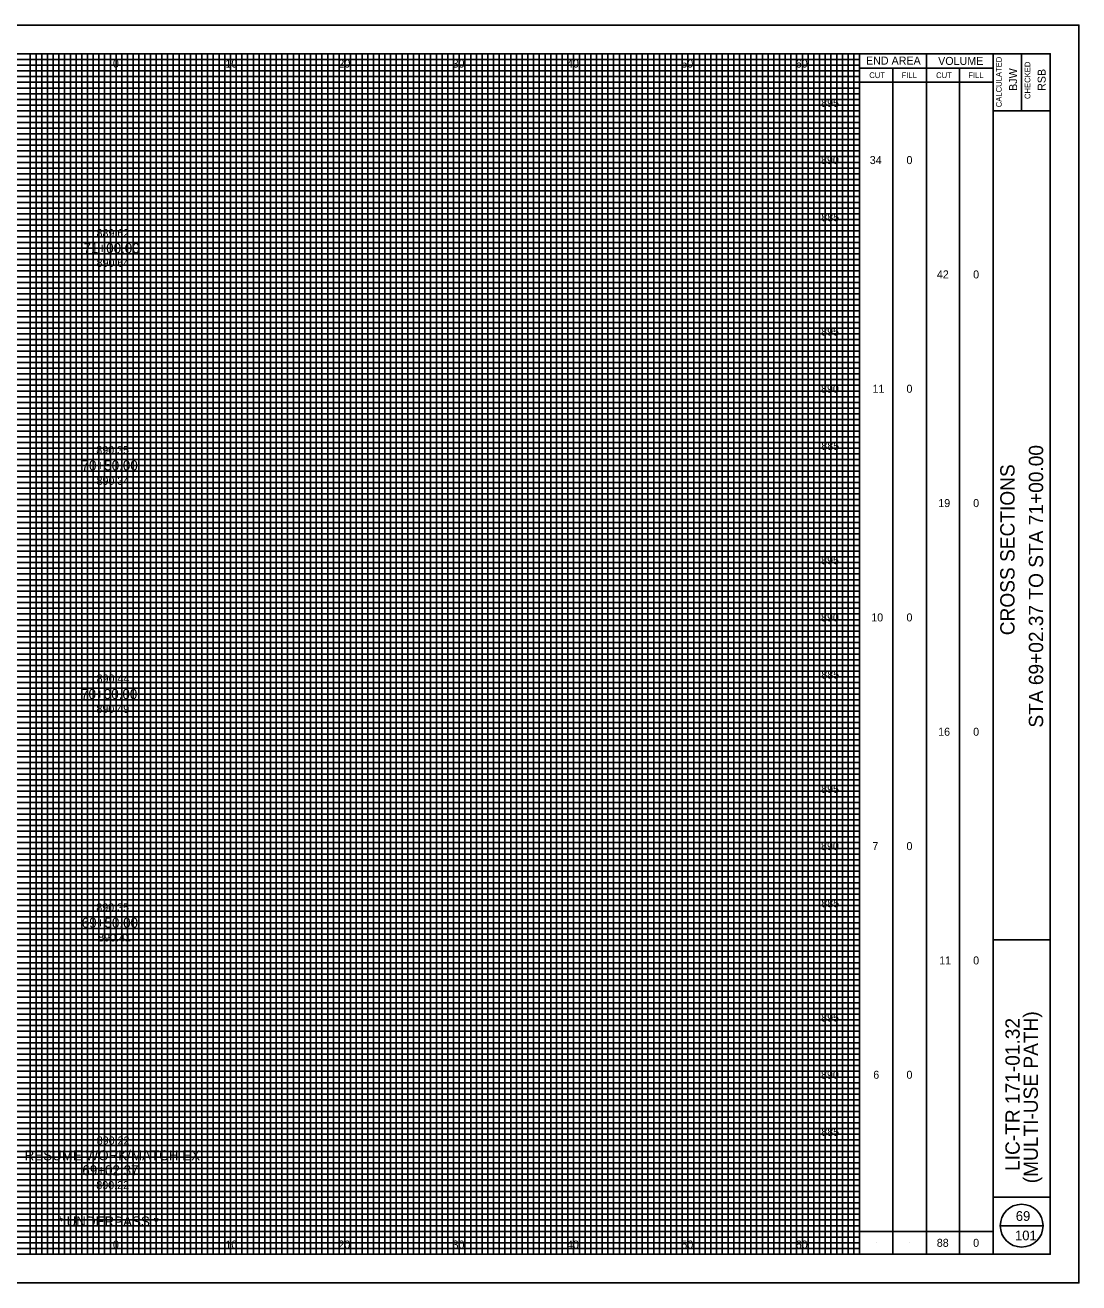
# Model space of a CAD drawing. Extents: x -10 to 160, y -2 to 3672.
# Drawn here: x 67.9 to 160, y -2.5 to 107.5 of the extents above; entities that cross this region are included whole.
import ezdxf

# ---------------------------------------------------------------- set-up
doc = ezdxf.new("R2010")
doc.units = 0
for name, color, linetype in [('SH_Border', 7, 'Continuous'), ('SH_Cut_Line', 7, 'Continuous'), ('SH_Data', 7, 'Continuous'), ('SH_Major_Grid_Line', 7, 'Continuous'), ('SH_Minor_Grid_Line', 7, 'Continuous'), ('SH_Text', 7, 'Continuous'), ('TX_P_10', 7, 'Continuous'), ('TX_X_10', 7, 'Continuous')]:
    doc.layers.add(name, color=color, linetype=linetype)

msp = doc.modelspace()

# ---------------------------------------------------------------- linework, layer by layer
at = {"layer": 'SH_Border'}
for p, q in [((152.5, 0), (152.5, 105)), ((155, 105), (155, 100)), ((152.5, 100), (157.5, 100)), ((152.5, 27.5), (157.5, 27.5)), ((152.5, 5), (157.5, 5))]:
    msp.add_line(p, q, dxfattribs=at)
msp.add_lwpolyline([(0, 105), (157.5, 105), (157.5, 0), (0, 0)], close=True, dxfattribs=at)
at = {"layer": 'SH_Cut_Line'}
msp.add_lwpolyline([(-10, -2.5), (160, -2.5), (160, 107.5), (-10, 107.5)], close=True, dxfattribs=at)
at = {"layer": 'SH_Data'}
for p, q in [((140.83, 0), (140.83, 105)), ((146.67, 0), (146.67, 105)), ((140.83, 103.75), (152.5, 103.75)), ((143.75, 0), (143.75, 103.75)), ((149.58, 0), (149.58, 103.75)), ((140.83, 102.5), (152.5, 102.5)), ((153.12, 2.5), (156.88, 2.5)), ((140.83, 2), (152.5, 2)), ((142.29, 1), (142.29, 1)), ((145.21, 1), (145.21, 1)), ((148.12, 1), (148.12, 1)), ((151.04, 1), (151.04, 1))]:
    msp.add_line(p, q, dxfattribs=at)
msp.add_circle((155, 2.5), 1.87, dxfattribs=at)
at = {"layer": 'SH_Major_Grid_Line'}
for p, q in [((70.83, 0), (70.83, 105)), ((75.83, 0), (75.83, 105)), ((80.83, 0), (80.83, 105)), ((85.83, 0), (85.83, 105)), ((90.83, 0), (90.83, 105)), ((95.83, 0), (95.83, 105)), ((100.83, 0), (100.83, 105)), ((105.83, 0), (105.83, 105)), ((110.83, 0), (110.83, 105)), ((115.83, 0), (115.83, 105)), ((120.83, 0), (120.83, 105)), ((125.83, 0), (125.83, 105)), ((130.83, 0), (130.83, 105)), ((135.83, 0), (135.83, 105)), ((5.83, 100), (140.83, 100)), ((5.83, 95), (140.83, 95)), ((5.83, 90), (140.83, 90)), ((5.83, 85), (140.83, 85)), ((5.83, 80), (140.83, 80)), ((5.83, 75), (140.83, 75)), ((5.83, 70), (140.83, 70)), ((5.83, 65), (140.83, 65)), ((5.83, 60), (140.83, 60)), ((5.83, 55), (140.83, 55)), ((5.83, 50), (140.83, 50)), ((5.83, 45), (140.83, 45)), ((5.83, 40), (140.83, 40)), ((5.83, 35), (140.83, 35)), ((5.83, 30), (140.83, 30)), ((5.83, 25), (140.83, 25)), ((5.83, 20), (140.83, 20)), ((5.83, 15), (140.83, 15)), ((5.83, 10), (140.83, 10)), ((5.83, 5), (140.83, 5))]:
    msp.add_line(p, q, dxfattribs=at)
at = {"layer": 'SH_Minor_Grid_Line'}
for p, q in [((68.33, 0), (68.33, 105)), ((68.83, 0), (68.83, 105)), ((69.33, 0), (69.33, 105)), ((69.83, 0), (69.83, 105)), ((70.33, 0), (70.33, 105)), ((71.33, 0), (71.33, 105)), ((71.83, 0), (71.83, 105)), ((72.33, 0), (72.33, 105)), ((72.83, 0), (72.83, 105)), ((73.33, 0), (73.33, 105)), ((73.83, 0), (73.83, 105)), ((74.33, 0), (74.33, 105)), ((74.83, 0), (74.83, 105)), ((75.33, 0), (75.33, 105)), ((76.33, 0), (76.33, 105)), ((76.83, 0), (76.83, 105)), ((77.33, 0), (77.33, 105)), ((77.83, 0), (77.83, 105)), ((78.33, 0), (78.33, 105)), ((78.83, 0), (78.83, 105)), ((79.33, 0), (79.33, 105)), ((79.83, 0), (79.83, 105)), ((80.33, 0), (80.33, 105)), ((81.33, 0), (81.33, 105)), ((81.83, 0), (81.83, 105)), ((82.33, 0), (82.33, 105)), ((82.83, 0), (82.83, 105)), ((83.33, 0), (83.33, 105)), ((83.83, 0), (83.83, 105)), ((84.33, 0), (84.33, 105)), ((84.83, 0), (84.83, 105)), ((85.33, 0), (85.33, 105)), ((86.33, 0), (86.33, 105)), ((86.83, 0), (86.83, 105)), ((87.33, 0), (87.33, 105)), ((87.83, 0), (87.83, 105)), ((88.33, 0), (88.33, 105)), ((88.83, 0), (88.83, 105)), ((89.33, 0), (89.33, 105)), ((89.83, 0), (89.83, 105)), ((90.33, 0), (90.33, 105)), ((91.33, 0), (91.33, 105)), ((91.83, 0), (91.83, 105)), ((92.33, 0), (92.33, 105)), ((92.83, 0), (92.83, 105)), ((93.33, 0), (93.33, 105)), ((93.83, 0), (93.83, 105)), ((94.33, 0), (94.33, 105)), ((94.83, 0), (94.83, 105)), ((95.33, 0), (95.33, 105)), ((96.33, 0), (96.33, 105)), ((96.83, 0), (96.83, 105)), ((97.33, 0), (97.33, 105)), ((97.83, 0), (97.83, 105)), ((98.33, 0), (98.33, 105)), ((98.83, 0), (98.83, 105)), ((99.33, 0), (99.33, 105)), ((99.83, 0), (99.83, 105)), ((100.33, 0), (100.33, 105)), ((101.33, 0), (101.33, 105)), ((101.83, 0), (101.83, 105)), ((102.33, 0), (102.33, 105)), ((102.83, 0), (102.83, 105)), ((103.33, 0), (103.33, 105)), ((103.83, 0), (103.83, 105)), ((104.33, 0), (104.33, 105)), ((104.83, 0), (104.83, 105)), ((105.33, 0), (105.33, 105)), ((106.33, 0), (106.33, 105)), ((106.83, 0), (106.83, 105)), ((107.33, 0), (107.33, 105)), ((107.83, 0), (107.83, 105)), ((108.33, 0), (108.33, 105)), ((108.83, 0), (108.83, 105)), ((109.33, 0), (109.33, 105)), ((109.83, 0), (109.83, 105)), ((110.33, 0), (110.33, 105)), ((111.33, 0), (111.33, 105)), ((111.83, 0), (111.83, 105)), ((112.33, 0), (112.33, 105)), ((112.83, 0), (112.83, 105)), ((113.33, 0), (113.33, 105)), ((113.83, 0), (113.83, 105)), ((114.33, 0), (114.33, 105)), ((114.83, 0), (114.83, 105)), ((115.33, 0), (115.33, 105)), ((116.33, 0), (116.33, 105)), ((116.83, 0), (116.83, 105)), ((117.33, 0), (117.33, 105)), ((117.83, 0), (117.83, 105)), ((118.33, 0), (118.33, 105)), ((118.83, 0), (118.83, 105)), ((119.33, 0), (119.33, 105)), ((119.83, 0), (119.83, 105)), ((120.33, 0), (120.33, 105)), ((121.33, 0), (121.33, 105)), ((121.83, 0), (121.83, 105)), ((122.33, 0), (122.33, 105)), ((122.83, 0), (122.83, 105)), ((123.33, 0), (123.33, 105)), ((123.83, 0), (123.83, 105)), ((124.33, 0), (124.33, 105)), ((124.83, 0), (124.83, 105)), ((125.33, 0), (125.33, 105)), ((126.33, 0), (126.33, 105)), ((126.83, 0), (126.83, 105)), ((127.33, 0), (127.33, 105)), ((127.83, 0), (127.83, 105)), ((128.33, 0), (128.33, 105)), ((128.83, 0), (128.83, 105)), ((129.33, 0), (129.33, 105)), ((129.83, 0), (129.83, 105)), ((130.33, 0), (130.33, 105)), ((131.33, 0), (131.33, 105)), ((131.83, 0), (131.83, 105)), ((132.33, 0), (132.33, 105)), ((132.83, 0), (132.83, 105)), ((133.33, 0), (133.33, 105)), ((133.83, 0), (133.83, 105)), ((134.33, 0), (134.33, 105)), ((134.83, 0), (134.83, 105)), ((135.33, 0), (135.33, 105)), ((136.33, 0), (136.33, 105)), ((136.83, 0), (136.83, 105)), ((137.33, 0), (137.33, 105)), ((137.83, 0), (137.83, 105)), ((138.33, 0), (138.33, 105)), ((138.83, 0), (138.83, 105)), ((139.33, 0), (139.33, 105)), ((139.83, 0), (139.83, 105)), ((140.33, 0), (140.33, 105)), ((5.83, 104.5), (140.83, 104.5)), ((5.83, 104), (140.83, 104)), ((5.83, 103.5), (140.83, 103.5)), ((5.83, 103), (140.83, 103)), ((5.83, 102.5), (140.83, 102.5)), ((5.83, 102), (140.83, 102)), ((5.83, 101.5), (140.83, 101.5)), ((5.83, 101), (140.83, 101)), ((5.83, 100.5), (140.83, 100.5)), ((5.83, 99.5), (140.83, 99.5)), ((5.83, 99), (140.83, 99)), ((5.83, 98.5), (140.83, 98.5)), ((5.83, 98), (140.83, 98)), ((5.83, 97.5), (140.83, 97.5)), ((5.83, 97), (140.83, 97)), ((5.83, 96.5), (140.83, 96.5)), ((5.83, 96), (140.83, 96)), ((5.83, 95.5), (140.83, 95.5)), ((5.83, 94.5), (140.83, 94.5)), ((5.83, 94), (140.83, 94)), ((5.83, 93.5), (140.83, 93.5)), ((5.83, 93), (140.83, 93)), ((5.83, 92.5), (140.83, 92.5)), ((5.83, 92), (140.83, 92)), ((5.83, 91.5), (140.83, 91.5)), ((5.83, 91), (140.83, 91)), ((5.83, 90.5), (140.83, 90.5)), ((5.83, 89.5), (140.83, 89.5)), ((5.83, 89), (140.83, 89)), ((5.83, 88.5), (140.83, 88.5)), ((5.83, 88), (140.83, 88)), ((5.83, 87.5), (140.83, 87.5)), ((5.83, 87), (140.83, 87)), ((5.83, 86.5), (140.83, 86.5)), ((5.83, 86), (140.83, 86)), ((5.83, 85.5), (140.83, 85.5)), ((5.83, 84.5), (140.83, 84.5)), ((5.83, 84), (140.83, 84)), ((5.83, 83.5), (140.83, 83.5)), ((5.83, 83), (140.83, 83)), ((5.83, 82.5), (140.83, 82.5)), ((5.83, 82), (140.83, 82)), ((5.83, 81.5), (140.83, 81.5)), ((5.83, 81), (140.83, 81)), ((5.83, 80.5), (140.83, 80.5)), ((5.83, 79.5), (140.83, 79.5)), ((5.83, 79), (140.83, 79)), ((5.83, 78.5), (140.83, 78.5)), ((5.83, 78), (140.83, 78)), ((5.83, 77.5), (140.83, 77.5)), ((5.83, 77), (140.83, 77)), ((5.83, 76.5), (140.83, 76.5)), ((5.83, 76), (140.83, 76)), ((5.83, 75.5), (140.83, 75.5)), ((5.83, 74.5), (140.83, 74.5)), ((5.83, 74), (140.83, 74)), ((5.83, 73.5), (140.83, 73.5)), ((5.83, 73), (140.83, 73)), ((5.83, 72.5), (140.83, 72.5)), ((5.83, 72), (140.83, 72)), ((5.83, 71.5), (140.83, 71.5)), ((5.83, 71), (140.83, 71)), ((5.83, 70.5), (140.83, 70.5)), ((5.83, 69.5), (140.83, 69.5)), ((5.83, 69), (140.83, 69)), ((5.83, 68.5), (140.83, 68.5)), ((5.83, 68), (140.83, 68)), ((5.83, 67.5), (140.83, 67.5)), ((5.83, 67), (140.83, 67)), ((5.83, 66.5), (140.83, 66.5)), ((5.83, 66), (140.83, 66)), ((5.83, 65.5), (140.83, 65.5)), ((5.83, 64.5), (140.83, 64.5)), ((5.83, 64), (140.83, 64)), ((5.83, 63.5), (140.83, 63.5)), ((5.83, 63), (140.83, 63)), ((5.83, 62.5), (140.83, 62.5)), ((5.83, 62), (140.83, 62)), ((5.83, 61.5), (140.83, 61.5)), ((5.83, 61), (140.83, 61)), ((5.83, 60.5), (140.83, 60.5)), ((5.83, 59.5), (140.83, 59.5)), ((5.83, 59), (140.83, 59)), ((5.83, 58.5), (140.83, 58.5)), ((5.83, 58), (140.83, 58)), ((5.83, 57.5), (140.83, 57.5)), ((5.83, 57), (140.83, 57)), ((5.83, 56.5), (140.83, 56.5)), ((5.83, 56), (140.83, 56)), ((5.83, 55.5), (140.83, 55.5)), ((5.83, 54.5), (140.83, 54.5)), ((5.83, 54), (140.83, 54)), ((5.83, 53.5), (140.83, 53.5)), ((5.83, 53), (140.83, 53)), ((5.83, 52.5), (140.83, 52.5)), ((5.83, 52), (140.83, 52)), ((5.83, 51.5), (140.83, 51.5)), ((5.83, 51), (140.83, 51)), ((5.83, 50.5), (140.83, 50.5)), ((5.83, 49.5), (140.83, 49.5)), ((5.83, 49), (140.83, 49)), ((5.83, 48.5), (140.83, 48.5)), ((5.83, 48), (140.83, 48)), ((5.83, 47.5), (140.83, 47.5)), ((5.83, 47), (140.83, 47)), ((5.83, 46.5), (140.83, 46.5)), ((5.83, 46), (140.83, 46)), ((5.83, 45.5), (140.83, 45.5)), ((5.83, 44.5), (140.83, 44.5)), ((5.83, 44), (140.83, 44)), ((5.83, 43.5), (140.83, 43.5)), ((5.83, 43), (140.83, 43)), ((5.83, 42.5), (140.83, 42.5)), ((5.83, 42), (140.83, 42)), ((5.83, 41.5), (140.83, 41.5)), ((5.83, 41), (140.83, 41)), ((5.83, 40.5), (140.83, 40.5)), ((5.83, 39.5), (140.83, 39.5)), ((5.83, 39), (140.83, 39)), ((5.83, 38.5), (140.83, 38.5)), ((5.83, 38), (140.83, 38)), ((5.83, 37.5), (140.83, 37.5)), ((5.83, 37), (140.83, 37)), ((5.83, 36.5), (140.83, 36.5)), ((5.83, 36), (140.83, 36)), ((5.83, 35.5), (140.83, 35.5)), ((5.83, 34.5), (140.83, 34.5)), ((5.83, 34), (140.83, 34)), ((5.83, 33.5), (140.83, 33.5)), ((5.83, 33), (140.83, 33)), ((5.83, 32.5), (140.83, 32.5)), ((5.83, 32), (140.83, 32)), ((5.83, 31.5), (140.83, 31.5)), ((5.83, 31), (140.83, 31)), ((5.83, 30.5), (140.83, 30.5)), ((5.83, 29.5), (140.83, 29.5)), ((5.83, 29), (140.83, 29)), ((5.83, 28.5), (140.83, 28.5)), ((5.83, 28), (140.83, 28)), ((5.83, 27.5), (140.83, 27.5)), ((5.83, 27), (140.83, 27)), ((5.83, 26.5), (140.83, 26.5)), ((5.83, 26), (140.83, 26)), ((5.83, 25.5), (140.83, 25.5)), ((5.83, 24.5), (140.83, 24.5)), ((5.83, 24), (140.83, 24)), ((5.83, 23.5), (140.83, 23.5)), ((5.83, 23), (140.83, 23)), ((5.83, 22.5), (140.83, 22.5)), ((5.83, 22), (140.83, 22)), ((5.83, 21.5), (140.83, 21.5)), ((5.83, 21), (140.83, 21)), ((5.83, 20.5), (140.83, 20.5)), ((5.83, 19.5), (140.83, 19.5)), ((5.83, 19), (140.83, 19)), ((5.83, 18.5), (140.83, 18.5)), ((5.83, 18), (140.83, 18)), ((5.83, 17.5), (140.83, 17.5)), ((5.83, 17), (140.83, 17)), ((5.83, 16.5), (140.83, 16.5)), ((5.83, 16), (140.83, 16)), ((5.83, 15.5), (140.83, 15.5)), ((5.83, 14.5), (140.83, 14.5)), ((5.83, 14), (140.83, 14)), ((5.83, 13.5), (140.83, 13.5)), ((5.83, 13), (140.83, 13)), ((5.83, 12.5), (140.83, 12.5)), ((5.83, 12), (140.83, 12)), ((5.83, 11.5), (140.83, 11.5)), ((5.83, 11), (140.83, 11)), ((5.83, 10.5), (140.83, 10.5)), ((5.83, 9.5), (140.83, 9.5)), ((5.83, 9), (140.83, 9)), ((5.83, 8.5), (140.83, 8.5)), ((5.83, 8), (140.83, 8)), ((5.83, 7.5), (140.83, 7.5)), ((5.83, 7), (140.83, 7)), ((5.83, 6.5), (140.83, 6.5)), ((5.83, 6), (140.83, 6)), ((5.83, 5.5), (140.83, 5.5)), ((5.83, 4.5), (140.83, 4.5)), ((5.83, 4), (140.83, 4)), ((5.83, 3.5), (140.83, 3.5)), ((5.83, 3), (140.83, 3)), ((5.83, 2.5), (140.83, 2.5)), ((5.83, 2), (140.83, 2)), ((5.83, 1.5), (140.83, 1.5)), ((5.83, 1), (140.83, 1)), ((5.83, 0.5), (140.83, 0.5))]:
    msp.add_line(p, q, dxfattribs=at)

# ---------------------------------------------------------------- texts
at = {"layer": 'SH_Data'}
for s, height, p in [('END AREA', 0.7, (141.39, 104.05)), ('VOLUME', 0.7, (147.7, 104.02)), ('CUT', 0.5, (141.68, 102.87)), ('FILL', 0.5, (144.5, 102.87)), ('CUT', 0.5, (147.52, 102.87)), ('FILL', 0.5, (150.34, 102.87)), ('69', 0.85, (154.49, 2.92)), ('101', 0.85, (154.42, 1.22))]:
    msp.add_text(s, height=height, dxfattribs=at).set_placement(p)
for s, height, p in [('CALCULATED', 0.5, (153.26, 100.32)), ('BJW', 0.7, (154.6, 101.75)), ('CHECKED', 0.5, (155.76, 101.04)), ('RSB', 0.7, (157.1, 101.75)), ('STA 69+02.37 TO STA 71+00.00', 1.25, (156.88, 46.06)), ('CROSS SECTIONS', 1.25, (154.38, 54.14)), ('(MULTI-USE PATH)', 1.25, (156.42, 6.21)), ('LIC-TR 171-01.32', 1.25, (154.83, 7.29))]:
    msp.add_text(s, height=height, rotation=90, dxfattribs=at).set_placement(p)
at = {"layer": 'SH_Text'}
for s, height, p in [('0', 0.7, (75.55, 103.79)), ('10', 0.7, (85.39, 103.79)), ('20', 0.7, (95.26, 103.79)), ('30', 0.7, (105.25, 103.79)), ('40', 0.7, (115.25, 103.79)), ('50', 0.7, (125.25, 103.79)), ('60', 0.7, (135.25, 103.79)), ('895', 0.7, (137.47, 100.35)), ('890', 0.7, (137.46, 95.35)), ('34', 0.7, (141.72, 95.35)), ('0', 0.7, (144.93, 95.35)), ('885', 0.7, (137.48, 90.35)), ('71+00.00', 0.875, (72.98, 87.56)), ('42', 0.7, (147.59, 85.35)), ('0', 0.7, (150.76, 85.35)), ('895', 0.7, (137.47, 80.35)), ('890', 0.7, (137.46, 75.35)), ('11', 0.7, (141.96, 75.35)), ('0', 0.7, (144.93, 75.35)), ('885', 0.7, (137.48, 70.35)), ('70+50.00', 0.875, (72.81, 68.56)), ('19', 0.7, (147.71, 65.35)), ('0', 0.7, (150.76, 65.35)), ('895', 0.7, (137.47, 60.35)), ('890', 0.7, (137.46, 55.35)), ('10', 0.7, (141.85, 55.35)), ('0', 0.7, (144.93, 55.35)), ('885', 0.7, (137.48, 50.35)), ('70+00.00', 0.875, (72.77, 48.56)), ('16', 0.7, (147.7, 45.35)), ('0', 0.7, (150.76, 45.35)), ('895', 0.7, (137.47, 40.35)), ('890', 0.7, (137.46, 35.35)), ('7', 0.7, (141.95, 35.35)), ('0', 0.7, (144.93, 35.35)), ('885', 0.7, (137.48, 30.35)), ('69+50.00', 0.875, (72.83, 28.56)), ('11', 0.7, (147.79, 25.35)), ('0', 0.7, (150.76, 25.35)), ('895', 0.7, (137.47, 20.35)), ('890', 0.7, (137.46, 15.35)), ('6', 0.7, (142.03, 15.35)), ('0', 0.7, (144.93, 15.35)), ('885', 0.7, (137.48, 10.35)), ('RESUME WORK/MATCH EX.', 0.875, (67.83, 8.22)), ('69+02.37', 0.875, (72.88, 6.91)), ('* UNDERPASS *', 0.875, (70.72, 2.43)), ('0', 0.7, (75.55, 0.5)), ('10', 0.7, (85.39, 0.5)), ('20', 0.7, (95.26, 0.5)), ('30', 0.7, (105.25, 0.5)), ('40', 0.7, (115.25, 0.5)), ('50', 0.7, (125.25, 0.5)), ('60', 0.7, (135.25, 0.5)), ('88', 0.7, (147.58, 0.65)), ('0', 0.7, (150.76, 0.65))]:
    msp.add_text(s, height=height, dxfattribs=at).set_placement(p)
at = {"layer": 'TX_P_10'}
for s, p in [('889.62', (74.12, 88.96)), ('890.35', (74.1, 69.99)), ('890.44', (74.13, 50.01)), ('890.35', (74.1, 29.99)), ('890.22', (74.14, 9.6))]:
    msp.add_text(s, height=0.7, dxfattribs=at).set_placement(p)
at = {"layer": 'TX_X_10'}
for s, p in [('890.64', (74.12, 86.36)), ('890.34', (74.12, 67.29)), ('890.49', (74.11, 47.35)), ('890.41', (74.26, 27.36)), ('890.22', (74.1, 5.7))]:
    msp.add_text(s, height=0.7, dxfattribs=at).set_placement(p)

doc.saveas('drawing.dxf')
